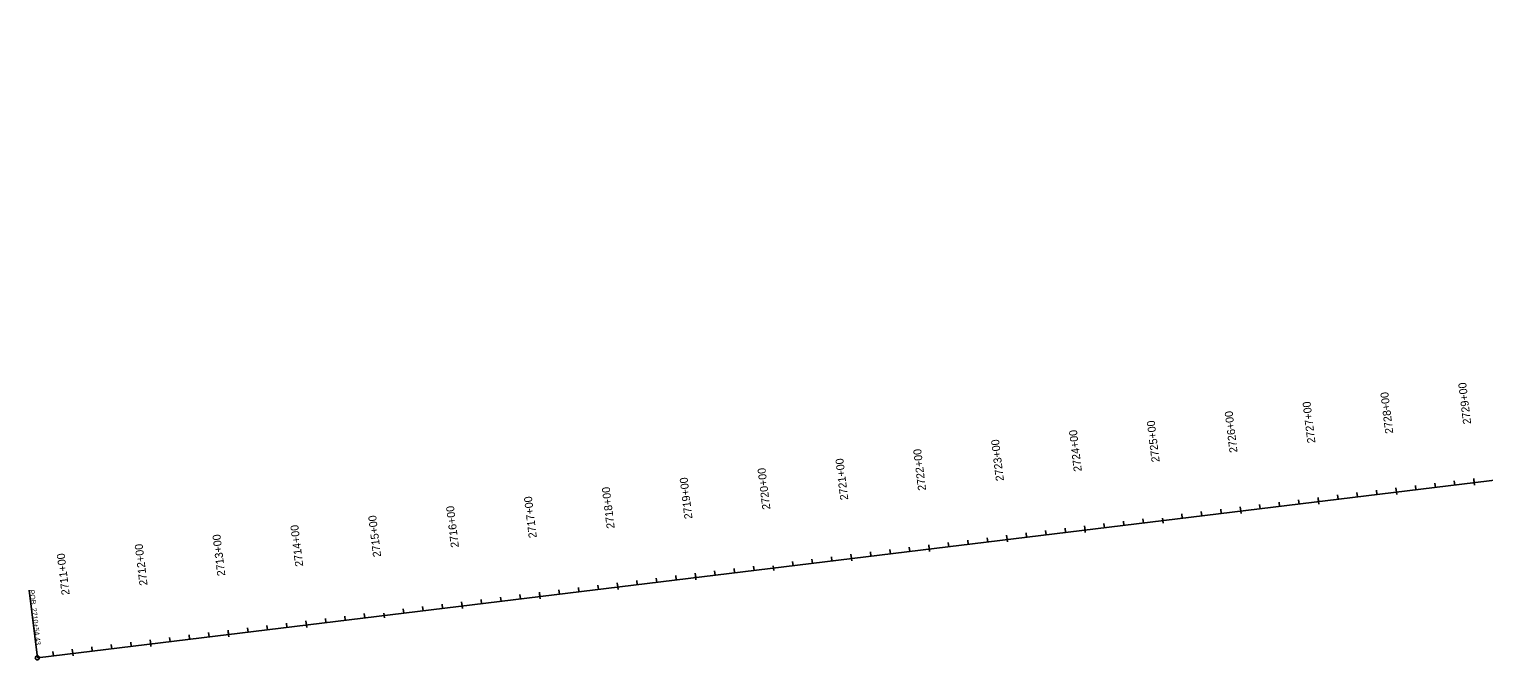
# Model space of a CAD drawing. Extents: x 18432127 to 18439586, y 7649485 to 7650472.
# Drawn here: x 18432127 to 18433981, y 7649485 to 7650289 of the extents above; entities that cross this region are included whole.
import ezdxf

# ---------------------------------------------------------------- set-up
doc = ezdxf.new("R2010")
doc.units = 0
for name, color, linetype in [('MeshTop', 7, 'Continuous'), ('Terrain', 7, 'Continuous'), ('TL_DNC', 7, 'Continuous'), ('TL_ShoulderTop', 7, 'Continuous')]:
    doc.layers.add(name, color=color, linetype=linetype)

msp = doc.modelspace()

# ---------------------------------------------------------------- linework, layer by layer
at = {"layer": 'MeshTop'}
for p, q in [((18433944.3, 7649707.9), (18433943.6, 7649713.4)), ((18433968.7, 7649714), (18433969.5, 7649707.9)), ((18433795.4, 7649689.8), (18433794.7, 7649695.2)), ((18433820.2, 7649692.8), (18433819.5, 7649698.2)), ((18433845, 7649695.8), (18433844.3, 7649701.3)), ((18433869.5, 7649701.9), (18433870.2, 7649695.8)), ((18433894.6, 7649701.9), (18433894, 7649707.3)), ((18433919.5, 7649704.9), (18433918.8, 7649710.3)), ((18433621.7, 7649668.6), (18433621, 7649674)), ((18433646.5, 7649671.7), (18433645.8, 7649677.1)), ((18433670.9, 7649677.7), (18433671.7, 7649671.6)), ((18433696.1, 7649677.7), (18433695.4, 7649683.1)), ((18433720.9, 7649680.7), (18433720.3, 7649686.1)), ((18433745.7, 7649683.7), (18433745.1, 7649689.2)), ((18433770.2, 7649689.8), (18433770.9, 7649683.7)), ((18433497.6, 7649653.5), (18433496.9, 7649658.9)), ((18433522.4, 7649656.5), (18433521.7, 7649662)), ((18433547.2, 7649659.6), (18433546.6, 7649665)), ((18433571.7, 7649665.6), (18433572.4, 7649659.5)), ((18433596.8, 7649665.6), (18433596.2, 7649671)), ((18433323.9, 7649632.3), (18433323.2, 7649637.8)), ((18433348.7, 7649635.4), (18433348, 7649640.8)), ((18433373.1, 7649641.4), (18433373.9, 7649635.4)), ((18433398.3, 7649641.4), (18433397.7, 7649646.8)), ((18433423.1, 7649644.4), (18433422.5, 7649649.9)), ((18433447.9, 7649647.5), (18433447.3, 7649652.9)), ((18433472.4, 7649653.5), (18433473.1, 7649647.4)), ((18433199.8, 7649617.2), (18433199.1, 7649622.6)), ((18433224.6, 7649620.2), (18433223.9, 7649625.7)), ((18433249.4, 7649623.3), (18433248.8, 7649628.7)), ((18433273.9, 7649629.3), (18433274.6, 7649623.3)), ((18433299, 7649629.3), (18433298.4, 7649634.7)), ((18433026.1, 7649596.1), (18433025.4, 7649601.5)), ((18433050.9, 7649599.1), (18433050.2, 7649604.5)), ((18433075.3, 7649605.1), (18433076.1, 7649599.1)), ((18433100.5, 7649605.1), (18433099.9, 7649610.5)), ((18433125.3, 7649608.2), (18433124.7, 7649613.6)), ((18433150.1, 7649611.2), (18433149.5, 7649616.6)), ((18433174.6, 7649617.2), (18433175.3, 7649611.2)), ((18432876.8, 7649581), (18432877.5, 7649574.9)), ((18432902, 7649580.9), (18432901.3, 7649586.4)), ((18432926.8, 7649584), (18432926.1, 7649589.4)), ((18432951.6, 7649587), (18432951, 7649592.4)), ((18432976.1, 7649593), (18432976.8, 7649587)), ((18433001.2, 7649593), (18433000.6, 7649598.5)), ((18432703.5, 7649556.7), (18432702.8, 7649562.2)), ((18432728.3, 7649559.8), (18432727.6, 7649565.2)), ((18432753.1, 7649562.8), (18432752.4, 7649568.2)), ((18432777.5, 7649568.9), (18432778.3, 7649562.8)), ((18432802.7, 7649568.8), (18432802.1, 7649574.3)), ((18432827.5, 7649571.9), (18432826.9, 7649577.3)), ((18432852.4, 7649574.9), (18432851.7, 7649580.3)), ((18432554.6, 7649538.6), (18432553.9, 7649544)), ((18432579, 7649544.7), (18432579.7, 7649538.6)), ((18432604.2, 7649544.7), (18432603.5, 7649550.1)), ((18432629, 7649547.7), (18432628.3, 7649553.1)), ((18432653.8, 7649550.7), (18432653.2, 7649556.1)), ((18432678.3, 7649556.8), (18432679, 7649550.7)), ((18432405.7, 7649520.5), (18432405, 7649525.9)), ((18432430.5, 7649523.5), (18432429.8, 7649528.9)), ((18432455.3, 7649526.5), (18432454.6, 7649531.9)), ((18432479.7, 7649532.6), (18432480.5, 7649526.5)), ((18432504.9, 7649532.6), (18432504.3, 7649538)), ((18432529.7, 7649535.6), (18432529.1, 7649541)), ((18432256.8, 7649502.3), (18432256.1, 7649507.7)), ((18432281.2, 7649508.4), (18432281.9, 7649502.3)), ((18432306.4, 7649508.4), (18432305.7, 7649513.8)), ((18432331.2, 7649511.4), (18432330.5, 7649516.8)), ((18432356, 7649514.4), (18432355.4, 7649519.8)), ((18432380.5, 7649520.5), (18432381.2, 7649514.4)), ((18432157.5, 7649490.2), (18432156.8, 7649495.6)), ((18432181.9, 7649496.3), (18432182.7, 7649490.2)), ((18432207.1, 7649496.3), (18432206.5, 7649501.7)), ((18432231.9, 7649499.3), (18432231.3, 7649504.7))]:
    msp.add_line(p, q, dxfattribs=at)
at = {"layer": 'Terrain'}
msp.add_line((18432137.1, 7649487.7), (18438712.4, 7650288.9), dxfattribs=at)
at = {"layer": 'TL_DNC'}
msp.add_line((18432137.1, 7649487.7), (18432126.6, 7649574.1), dxfattribs=at)
msp.add_circle((18432137.1, 7649487.7), 2.67, dxfattribs=at)
at = {"layer": 'TL_ShoulderTop'}
for p, q in [((18433969.1, 7649711), (18433968.4, 7649716.4)), ((18433770.6, 7649686.8), (18433769.9, 7649692.2)), ((18433869.8, 7649698.9), (18433869.2, 7649704.3)), ((18433671.3, 7649674.7), (18433670.6, 7649680.1)), ((18433472.8, 7649650.5), (18433472.1, 7649655.9)), ((18433571.7, 7649665.6), (18433572.4, 7649659.5)), ((18433373.5, 7649638.4), (18433372.8, 7649643.8)), ((18433175, 7649614.2), (18433174.3, 7649619.6)), ((18433274.2, 7649626.3), (18433273.6, 7649631.7)), ((18433075.3, 7649605.1), (18433076.1, 7649599.1)), ((18432877.2, 7649577.9), (18432876.5, 7649583.3)), ((18432976.4, 7649590), (18432975.8, 7649595.4)), ((18432777.9, 7649565.8), (18432777.2, 7649571.2)), ((18432579, 7649544.7), (18432579.7, 7649538.6)), ((18432678.6, 7649553.7), (18432678, 7649559.1)), ((18432480.1, 7649529.5), (18432479.4, 7649535)), ((18432281.6, 7649505.3), (18432280.9, 7649510.8)), ((18432380.8, 7649517.4), (18432380.2, 7649522.9)), ((18432182.3, 7649493.2), (18432181.6, 7649498.7))]:
    msp.add_line(p, q, dxfattribs=at)

# ---------------------------------------------------------------- texts
at = {"layer": 'MeshTop'}
for s, p in [('2728+00', (18433865.8, 7649773.9)), ('2729+00', (18433965.1, 7649786)), ('2727+00', (18433766.6, 7649761.8)), ('2725+00', (18433568, 7649737.6)), ('2726+00', (18433667.3, 7649749.7)), ('2724+00', (18433468.8, 7649725.6)), ('2722+00', (18433270.2, 7649701.4)), ('2723+00', (18433369.5, 7649713.5)), ('2720+00', (18433071.7, 7649677.2)), ('2721+00', (18433171, 7649689.3)), ('2719+00', (18432972.4, 7649665.1)), ('2717+00', (18432773.9, 7649640.9)), ('2718+00', (18432873.2, 7649653)), ('2716+00', (18432674.6, 7649628.8)), ('2714+00', (18432476.1, 7649604.6)), ('2715+00', (18432575.4, 7649616.7)), ('2713+00', (18432376.8, 7649592.5)), ('2711+00', (18432178.3, 7649568.3)), ('2712+00', (18432277.6, 7649580.4))]:
    msp.add_text(s, height=10.2, rotation=96.947, dxfattribs=at).set_placement(p)
at = {"layer": 'TL_DNC'}
for s, p in [('POB ', (18432126.7, 7649574.1)), ('2710+54.43', (18432129.5, 7649550.9))]:
    msp.add_text(s, height=6.48, rotation=276.947, dxfattribs=at).set_placement(p)
at = {"layer": 'TL_ShoulderTop'}
for s, p in [('2725+00', (18433568, 7649737.6)), ('2720+00', (18433071.7, 7649677.2)), ('2715+00', (18432575.4, 7649616.7))]:
    msp.add_text(s, height=10.2, rotation=96.947, dxfattribs=at).set_placement(p)

doc.saveas('drawing.dxf')
